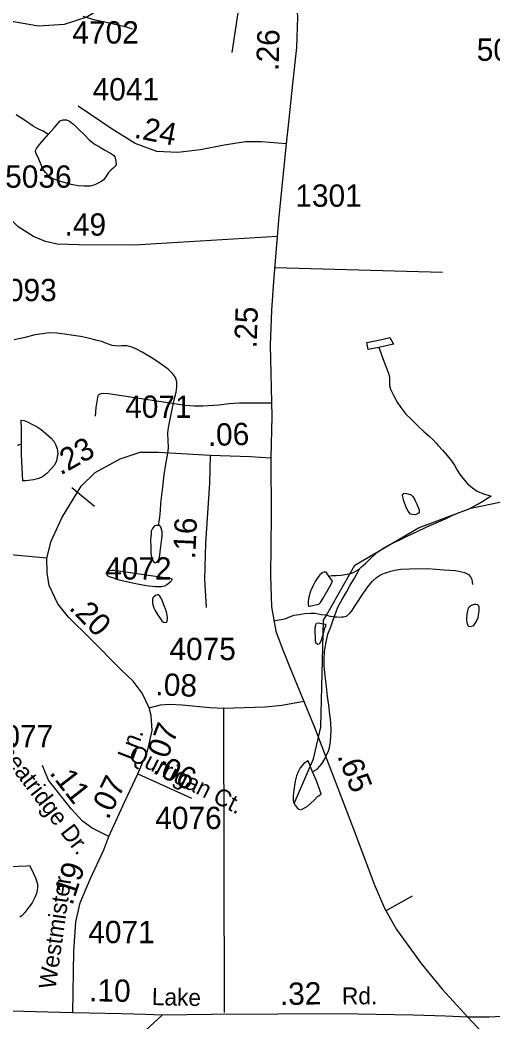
# Model space of a CAD drawing. Extents: x 2001466 to 2224147, y 644118 to 847247.
# Drawn here: x 2062991 to 2065640, y 683500 to 689110 of the extents above; entities that cross this region are included whole.
import ezdxf

# ---------------------------------------------------------------- set-up
doc = ezdxf.new("R2010")
doc.units = 0
for name, color, linetype in [('Exist Hydrographic Misc Water Feature', 7, 'Continuous'), ('Exist Road Non-System Type 51', 7, 'Continuous'), ('Exist Road Secondary Mileage Hundredths English Label', 7, 'Continuous'), ('Exist Road Secondary Type 51 Attributed', 7, 'Continuous'), ('Exist Road Secondary Type 51 Label', 7, 'Continuous'), ('Exist Road Secondary Type 51 Number Label', 7, 'Continuous')]:
    doc.layers.add(name, color=color, linetype=linetype)

msp = doc.modelspace()

# ---------------------------------------------------------------- linework, layer by layer
at = {"layer": 'Exist Hydrographic Misc Water Feature'}
for points in [[(2063621.2, 689058.4), (2063593.1, 689068.3), (2063571, 689074.1), (2063515.2, 689088.2), (2063465, 689097.9), (2063410.8, 689110.1), (2063344.8, 689129.9)], [(2063150.2, 688471.4), (2063140.1, 688475.4), (2063120.1, 688487.4), (2063090.1, 688501.6), (2063063.9, 688515.4), (2063022, 688545.2), (2062970, 688579.1)], [(2063150.2, 688471.4), (2063182, 688507.6), (2063216, 688545.8), (2063231.8, 688551.6), (2063250.3, 688551.6), (2063267.9, 688543.6), (2063292.3, 688525.8), (2063320.4, 688498), (2063350.1, 688470), (2063380.5, 688438.2), (2063412, 688413.9), (2063436.2, 688400.1), (2063466.4, 688382.1), (2063498.2, 688364.4), (2063514.4, 688354.2), (2063522.6, 688344.4), (2063528.3, 688320.4), (2063528.7, 688302.1), (2063524.4, 688292.2), (2063512.7, 688280.2), (2063498.6, 688270.2), (2063486.5, 688256.2), (2063470.7, 688232.3), (2063458.6, 688216.2), (2063448.3, 688208.1), (2063432.8, 688198.3), (2063409, 688188.1), (2063382.9, 688180.2), (2063350.5, 688179.9), (2063316.5, 688181.8), (2063276.5, 688189.9), (2063218.9, 688205.9), (2063174.8, 688221.5), (2063158.6, 688231.7), (2063148.6, 688239.7), (2063132.8, 688257.5), (2063118.6, 688277.5), (2063096.7, 688331.5), (2063080.1, 688367.7), (2063076.6, 688379.6), (2063082.3, 688391.3), (2063102.4, 688415.4), (2063150.2, 688471.4)], [(2063766, 686281.1), (2063768.2, 686291.3), (2063770.1, 686303.2), (2063774.2, 686327.3), (2063778.1, 686363.3), (2063779.9, 686405.1), (2063785.9, 686449.3), (2063791.4, 686495), (2063797.8, 686563.1), (2063807.8, 686623.2), (2063817.4, 686673.2), (2063821.5, 686713.2), (2063820.9, 686761.2), (2063819.3, 686787.4), (2063819.3, 686799.1), (2063823, 686829.4), (2063836.9, 686903.1), (2063849, 686957.2), (2063856.8, 686991.4), (2063864.8, 687027.5), (2063868.7, 687057.3), (2063868.5, 687085.3), (2063860.7, 687109.2), (2063844.3, 687131.2), (2063820.3, 687155.1), (2063776.2, 687186.9), (2063734.2, 687214.8), (2063674.3, 687250.6), (2063640.3, 687268.8), (2063616.5, 687278.5), (2063590.2, 687286.5), (2063560.5, 687286.6), (2063540.6, 687284.7), (2063506.4, 687288.7), (2063470.5, 687300.6), (2063446.3, 687310.3), (2063422.1, 687316.4), (2063402.2, 687322.3), (2063364.1, 687330.1), (2063330.4, 687338), (2063290.2, 687344.1), (2063240.2, 687352.1), (2063196.1, 687358), (2063152.2, 687359.8), (2063116.4, 687353.9), (2063074.1, 687347.7), (2063020.4, 687333.6), (2062958.1, 687319.5)], [(2065000.2, 687277.2), (2064939.9, 687265.2), (2064933.7, 687305.1), (2065018, 687321.1), (2065061.9, 687333.6), (2065081.8, 687295.6), (2065000.2, 687277.2)], [(2065000.2, 687277.2), (2065010.2, 687253.3), (2065018.2, 687229.4), (2065037.9, 687175.3), (2065054.3, 687133.5), (2065060.3, 687109.5), (2065060.5, 687085.5), (2065060.7, 687063.6), (2065066.6, 687043.6), (2065084.5, 687005.6), (2065102.7, 686971.6), (2065122.8, 686941.8), (2065152.5, 686903.6), (2065178.8, 686877.7), (2065220.6, 686835.7), (2065252.8, 686806.1), (2065282.7, 686780.1), (2065305.1, 686760.1), (2065320.7, 686741.9), (2065335, 686725.9), (2065357, 686702.3), (2065380.8, 686674.4), (2065401.5, 686650.1), (2065423.4, 686618.4), (2065439.2, 686590.4), (2065455.6, 686564.5), (2065479.6, 686534.5), (2065497.4, 686514.3), (2065525.7, 686490.5), (2065551.2, 686472.5), (2065587.4, 686458.4), (2065619.4, 686448.8), (2065629.5, 686444.8)], [(2064707, 685778.8), (2064865.9, 686058.3), (2065222.9, 686267.6), (2065514.9, 686376.5), (2065805.8, 686436.2), (2066222.7, 686460.5), (2066438.8, 686518.5), (2066613.7, 686777.4), (2066871.9, 686913.2)], [(2062999.5, 686733.6), (2062999.3, 686819.6), (2062997.4, 686869.4), (2063013.2, 686867.7), (2063033.1, 686861.5), (2063061, 686845.9), (2063087.2, 686831.8), (2063109.6, 686817.9), (2063137.5, 686793.8), (2063165.4, 686770.1), (2063179.7, 686752.1), (2063191.4, 686730), (2063199.6, 686710.1), (2063201.7, 686682.2), (2063199.6, 686662.3), (2063195.5, 686642.2), (2063183.8, 686618), (2063166, 686598), (2063141.6, 686572.1), (2063115.7, 686552.1), (2063095.7, 686543.7), (2063065.9, 686535.7), (2063038, 686531.8), (2063022, 686529.8), (2063005.8, 686529.8), (2062999.5, 686675.5), (2062999.5, 686733.6)], [(2062999.5, 686733.6), (2062993.5, 686733.7), (2062975.5, 686727.5)], [(2064892.1, 686037.4), (2064904.2, 686049.3), (2064928, 686069.7), (2064958.1, 686099.6), (2064994.4, 686133.4), (2065032, 686157.7), (2065066, 686175.7), (2065114, 686197.7), (2065160.1, 686219.9), (2065212.2, 686244), (2065270, 686272.2), (2065333.8, 686300.2), (2065377.9, 686320.3), (2065419.5, 686340.3), (2065465.4, 686358.5), (2065503.6, 686372.6), (2065551.6, 686398.6), (2065583.5, 686416.5), (2065615.3, 686436.8), (2065629.5, 686444.8)], [(2065213.4, 686400), (2065225.7, 686368.1), (2065225.9, 686362), (2065225.9, 686351.8), (2065221.4, 686348.1), (2065215.7, 686344.1), (2065201.7, 686339.7), (2065189.8, 686341.9), (2065177.8, 686343.7), (2065165.7, 686359.8), (2065154, 686381.8), (2065139.6, 686417.6), (2065133.5, 686447.8), (2065133.7, 686453.8), (2065139.8, 686459.8), (2065147.8, 686461.8), (2065163.6, 686457.8), (2065181.9, 686451.8), (2065191.7, 686441.8), (2065199.5, 686428), (2065205.6, 686413.7), (2065213.4, 686400)], [(2063766, 686281.1), (2063752.4, 686281.1), (2063742.4, 686277), (2063731.9, 686263.1), (2063726.2, 686249), (2063724.5, 686231), (2063722.3, 686203), (2063722.5, 686155.1), (2063724.3, 686123.1), (2063726.6, 686102.9), (2063730.5, 686091.4), (2063736.4, 686081.2), (2063740.5, 686075.3), (2063744.4, 686073.1), (2063750.6, 686073.4), (2063756.3, 686075.3), (2063766.6, 686085.2), (2063772.1, 686101.3), (2063776.6, 686133.1), (2063784, 686193.2), (2063786.3, 686221.3), (2063786.3, 686245.2), (2063782.2, 686265.3), (2063778.3, 686275.2), (2063770.3, 686281.3), (2063766, 686281.1)], [(2063660.8, 686009.1), (2063838.8, 685983.3), (2063840.8, 685977.3), (2063836.9, 685969.4), (2063832.4, 685963.2), (2063820.5, 685953.2), (2063812.7, 685947.1), (2063800.8, 685941.2), (2063782.6, 685937.5), (2063748.7, 685937.4), (2063696.9, 685943.2), (2063630.8, 685954.8), (2063570.8, 685968.8), (2063541, 685976.9), (2063510.9, 685986.8), (2063492.6, 685992.8), (2063484.8, 685996.8), (2063478.5, 686002.6), (2063482.8, 686014.6), (2063486.5, 686024.6), (2063492.6, 686028.9), (2063504.5, 686030.8), (2063518.5, 686030.7), (2063542.7, 686027), (2063660.8, 686009.1)], [(2064720.5, 685996.9), (2064706.3, 686018.9), (2064694.4, 686019.1), (2064686.4, 686017.1), (2064670.5, 686004.9), (2064658.8, 685988.8), (2064644.4, 685967), (2064630.3, 685940.8), (2064618.6, 685913), (2064608.5, 685878.8), (2064604.8, 685857), (2064604.8, 685838.8), (2064606.9, 685828.7), (2064610.8, 685829), (2064664.7, 685839), (2064674.6, 685848.9), (2064688.7, 685873.1), (2064732.8, 685951.2), (2064740.4, 685969.1), (2064720.5, 685996.9)], [(2064628.4, 684901.1), (2064654.5, 684915), (2064668.6, 684931.1), (2064680.3, 684945.2), (2064698.1, 684973.3), (2064708.2, 684995.3), (2064716.4, 685013.1), (2064724.2, 685035.4), (2064730.3, 685071.4), (2064734.2, 685133.3), (2064732.2, 685179.4), (2064725.8, 685221.4), (2064719.7, 685273.4), (2064713.5, 685323.4), (2064707.6, 685379.1), (2064699.8, 685439.1), (2064693.4, 685493.2), (2064693.4, 685530.9), (2064695.3, 685573.2), (2064703.1, 685617.1), (2064714.9, 685671.2), (2064730.9, 685713), (2064746.7, 685757.3), (2064760.7, 685797.3), (2064770.5, 685823.4), (2064782.8, 685843), (2064796.6, 685869.4), (2064810.7, 685891.1), (2064821, 685911.1), (2064840.6, 685945.4), (2064864.2, 685985.2), (2064882.3, 686019.4), (2064892.1, 686037.4)], [(2064720.5, 685996.9), (2064738.1, 686001.1), (2064760.7, 686000.9), (2064790.4, 686001.3), (2064822.6, 686007.4), (2064848.6, 686013.2), (2064864.4, 686021.3), (2064880.6, 686029.4), (2064892.1, 686037.4)], [(2063760.8, 685781.4), (2063777.2, 685757.4), (2063785.4, 685747.2), (2063795.1, 685739.3), (2063802.9, 685737.3), (2063811.3, 685739.3), (2063815.4, 685743.5), (2063817, 685763.5), (2063815, 685777.2), (2063811.1, 685797.3), (2063800.8, 685827.2), (2063782.8, 685869.3), (2063773.1, 685885.4), (2063764.7, 685891.1), (2063758.8, 685891.2), (2063749.2, 685889), (2063736.9, 685877.1), (2063733.2, 685867.1), (2063733.2, 685857), (2063733, 685845.2), (2063735, 685835.2), (2063741, 685819.3), (2063748.9, 685801.4), (2063760.8, 685781.4)], [(2065492.7, 685784.5), (2065491.1, 685754.8), (2065492.7, 685734.6), (2065494.8, 685730.7), (2065499.1, 685720.7), (2065502.6, 685716.5), (2065515.1, 685714.6), (2065524.7, 685718.8), (2065532.7, 685720.9), (2065542.5, 685734.8), (2065548.7, 685748.9), (2065556.5, 685764.7), (2065558.7, 685778.5), (2065562.4, 685800.7), (2065562.6, 685822.6), (2065558.9, 685832.5), (2065554.4, 685836.8), (2065546.6, 685838.8), (2065534.7, 685838.6), (2065519, 685832.5), (2065508.7, 685824.7), (2065500.5, 685816.6), (2065496.4, 685802.6), (2065492.7, 685784.5)], [(2064526.7, 684723.4), (2064633.7, 684973.8), (2064675.8, 685150.2), (2064690.8, 685750.2), (2064707, 685778.8)], [(2064677.4, 685638.8), (2064673.1, 685628.9), (2064665.9, 685616.6), (2064659, 685613.2), (2064653.2, 685616.9), (2064648.9, 685619.2), (2064645.4, 685633.1), (2064645.4, 685651), (2064644.8, 685689.1), (2064644.8, 685709), (2064647.1, 685722.9), (2064649.1, 685729.1), (2064651, 685732.8), (2064659, 685734.9), (2064701, 685727.3), (2064701, 685717.1), (2064695.1, 685699), (2064688.9, 685673.1), (2064677.4, 685638.8)], [(2064628.4, 684901.1), (2064604.2, 684963.2), (2064580.2, 684947), (2064560.5, 684923.2), (2064548.4, 684901.1), (2064538.8, 684879), (2064532.5, 684849.1), (2064528.6, 684825), (2064522.6, 684784.9), (2064520.8, 684762.9), (2064521.2, 684745), (2064522.6, 684731), (2064531, 684715.1), (2064542.7, 684699.1), (2064553, 684691.1), (2064561.2, 684689.1), (2064570.6, 684692.8), (2064598.9, 684707.3), (2064638.5, 684743), (2064656.7, 684763.4), (2064664.7, 684767), (2064677, 684777.3), (2064650.6, 684851.1), (2064628.4, 684901.1)], [(2062931.8, 684371.8), (2063029.8, 684374), (2063043.8, 684376.3), (2063054, 684360.2), (2063078, 684308.3), (2063088.1, 684274.3), (2063088.3, 684252.4), (2063086.2, 684238.1), (2063082.1, 684220.5), (2063072.3, 684194.4), (2063058.5, 684168.1), (2063040.5, 684144.1), (2063018.3, 684114.1), (2063000.3, 684094.2), (2062990.5, 684086.4)]]:
    msp.add_lwpolyline(points, dxfattribs=at)
at = {"layer": 'Exist Road Non-System Type 51'}
for p, q in [((2064417.1, 687725), (2065356.9, 687698.5)), ((2063281.1, 686493.2), (2063408.4, 686388.4)), ((2064130.8, 685257.1), (2064133.3, 683552.8))]:
    msp.add_line(p, q, dxfattribs=at)
for points in [[(2063805.6, 689732.4), (2063944.2, 689695.4), (2064044.4, 689640.5), (2064115.5, 689569.3), (2064199.5, 689433.5), (2064222.1, 689346.2), (2064222.1, 689226.5), (2064176.9, 688929)], [(2063414.4, 686892), (2063417.3, 686940), (2063426.5, 686997.8), (2063430.8, 687011.7), (2063445, 687019.4), (2063457, 687021.2), (2063487, 687018.5), (2063915.6, 686953.8), (2063967.6, 686950.7), (2064015.6, 686949.8), (2064105.7, 686955.9), (2064159.8, 686962.8), (2064219.9, 686967.6), (2064399.7, 686967.9)], [(2064707, 685778.8), (2064727.5, 685773.2), (2064755.4, 685768.7), (2064765.4, 685768.5), (2064783.4, 685766.1), (2064793.4, 685767.9), (2064801.5, 685769.7), (2064819.5, 685773.4), (2064837.9, 685789), (2064850.2, 685804.7), (2064862.5, 685822.5), (2064872.9, 685840.3), (2064912.1, 685899.5), (2064938.9, 685936.9), (2064965.5, 685968.4), (2064988, 685989.9), (2065004.2, 685999.6), (2065022.4, 686009.2), (2065032.4, 686013), (2065050.6, 686018.7), (2065060.6, 686022.5), (2065090.8, 686029.8), (2065122.9, 686035.2), (2065173, 686038.2), (2065273, 686040.1), (2065366.8, 686032.2), (2065430.8, 686028.9), (2065480.5, 686017.9), (2065492.4, 686011.7), (2065502.3, 686005.5), (2065514, 685993.2), (2065517.9, 685985.1), (2065521.7, 685977.1), (2065525.1, 685949)], [(2064411, 685745.6), (2064473.2, 685758.4), (2064523.6, 685777.4), (2064553.7, 685782.8), (2064583.8, 685788.2), (2064617.9, 685789.5), (2064643.9, 685788.9), (2064677.7, 685782.3), (2064703.7, 685779.7), (2064707, 685778.8)], [(2064130.8, 685257.1), (2064363.6, 685265.3), (2064457.1, 685274.3), (2064582.5, 685296.8)], [(2065045.5, 684126.3), (2065188.6, 684205.9)]]:
    msp.add_lwpolyline(points, dxfattribs=at)
at = {"layer": 'Exist Road Secondary Type 51 Attributed'}
for points in [[(2064306.6, 689747.5), (2064354, 689676), (2064445.1, 689537.9), (2064498, 689407.6), (2064535.1, 689250.5), (2064544.5, 689128.9), (2064539.8, 688956.7), (2064517.3, 688753.8), (2064495.6, 688554.9), (2064480.6, 688417.5)], [(2063642.3, 689406), (2063574.9, 689293.1), (2063478.6, 689198.3), (2063365, 689127.3), (2063237.2, 689086.2), (2063095.1, 689076.8), (2062954.7, 689100.4), (2062794.1, 689151), (2062684.5, 689164.4), (2062584.3, 689154.1), (2062486.8, 689132)], [(2064480.6, 688417.5), (2064341.8, 688427.7), (2064253.4, 688429.3), (2064133.5, 688410.4), (2064002.5, 688383.5), (2063874.7, 688369.3), (2063756.3, 688374.1), (2063636, 688419.1), (2063506.6, 688499.6), (2063316.1, 688628.3)], [(2064431.7, 687898.2), (2063630.2, 687849.6), (2063319.5, 687851.2), (2063198.8, 687855), (2063132.6, 687870.6), (2063066.4, 687897.9), (2062980.8, 687952.4), (2062922.4, 688010.9), (2062864, 688096.6), (2062801.7, 688221.2), (2062743.3, 688330.3), (2062700.5, 688396.5), (2062657.7, 688437.8), (2062599.7, 688480.5), (2062505.8, 688514.6), (2062145.7, 688598.9)], [(2064480.6, 688417.5), (2064441.2, 688010.9), (2064431.7, 687898.2)], [(2064431.7, 687898.2), (2064410.4, 687646.1), (2064399.4, 687485), (2064391.5, 687290.8), (2064401.7, 686889.7), (2064395.4, 686659.2)], [(2063141.7, 686097), (2063165.8, 686191.8), (2063225.7, 686322.8), (2063333, 686499.7), (2063412.3, 686576.3), (2063551.2, 686654.4), (2063663.2, 686690), (2063765.8, 686690), (2064056.2, 686674.2)], [(2064056.2, 686674.2), (2064051.8, 686517.1), (2064028.9, 686180.7), (2064024.6, 685979.4), (2064032.9, 685821.5)], [(2064056.2, 686674.2), (2064279.8, 686666.3), (2064395.4, 686659.2)], [(2064395.4, 686659.2), (2064397, 686333.9), (2064394.6, 685997.5), (2064399.4, 685825.4), (2064423.3, 685689.1), (2064458.3, 685594.1), (2064500.7, 685490.3), (2064638.4, 685154.3), (2064866.5, 684560.5), (2064974.7, 684271.4), (2065031.7, 684136.9), (2065098.9, 684018.5), (2065237.7, 683827.1), (2065354.7, 683683.4), (2065499, 683527.8)], [(2063141.7, 686097), (2062958.6, 686114.4), (2062753.5, 686138.1), (2062621, 686161.8)], [(2063713.9, 685259.6), (2063674.3, 685342.2), (2063624.6, 685407.7), (2063559.9, 685469.3), (2063383.5, 685647.8), (2063262.8, 685767.8), (2063202.8, 685841.2), (2063154.3, 685943.8), (2063142.5, 686015.7), (2063141.7, 686097)], [(2063713.9, 685259.6), (2063778.3, 685275.5), (2063826.2, 685280.7), (2063898.1, 685275.5), (2064053, 685260.8), (2064130.8, 685257.1)], [(2063651.2, 684888.9), (2063705, 685016.9), (2063731.5, 685133), (2063726, 685215.9), (2063713.9, 685259.6)], [(2063488.7, 684539.7), (2063395.6, 684585.5), (2063340.4, 684625), (2063277.2, 684694.5), (2063150.6, 684854), (2063117.5, 684936.9)], [(2063488.7, 684539.7), (2063575.3, 684731.9), (2063651.2, 684888.9)], [(2063651.2, 684888.9), (2063951.8, 684753.3)], [(2063286, 683551.6), (2063291.6, 683895.7), (2063302.7, 684061.6), (2063327.4, 684168.1), (2063383.5, 684300.8), (2063459.3, 684464.2), (2063488.7, 684539.7)], [(2067078.2, 684058), (2066921.2, 684007.6), (2066719.6, 683929.4), (2066353.7, 683777.4), (2066101, 683672.1), (2065928.6, 683602), (2065775.1, 683547.8), (2065689.8, 683530.3), (2065618.2, 683526.5), (2065499, 683527.8)], [(2063286, 683551.6), (2063077.7, 683557.9), (2062681.2, 683567.9), (2062329.2, 683574.2)], [(2062552.8, 681509.3), (2062603.2, 681588.2), (2062728.7, 681777.3), (2062829.7, 681925.7), (2062903.8, 682052), (2062974.8, 682205.2), (2063019, 682313), (2063075, 682472.4), (2063127.1, 682698.2), (2063169.7, 682896.8), (2063208.4, 682980.5), (2063244.6, 683045.2), (2063312.5, 683113.1), (2063440.3, 683234.7), (2063629.7, 683395.4), (2063787.4, 683539.1)], [(2063787.4, 683539.1), (2063693.2, 683542.8), (2063559, 683545.3), (2063286, 683551.6)], [(2065499, 683527.8), (2065374.8, 683532.8), (2065192.8, 683539.1), (2064778.1, 683546.6), (2064434.9, 683544.1), (2064063.4, 683541.6), (2063787.4, 683539.1)], [(2065499, 683527.8), (2065653.4, 683360.8), (2065812, 683171.5)]]:
    msp.add_lwpolyline(points, dxfattribs=at)

# ---------------------------------------------------------------- texts
at = {"layer": 'Exist Road Secondary Mileage Hundredths English Label'}
for s, rotation, p in [('.26', 88.4245, (2064438.7, 688824.8)), ('.24', 348.526, (2063625.6, 688452.7)), ('.49', 359.7135, (2063240.1, 687903.8)), ('.25', 87.9498, (2064315.1, 687271.2)), ('.06', 1.5915, (2064044, 686725.1)), ('.23', 29.3633, (2063217.4, 686559.5)), ('.16', 87.3499, (2063971.8, 686090.1)), ('.20', 314.5975, (2063260.1, 685815)), ('.08', 357.5534, (2063747.4, 685330.4)), ('.07', 69.154, (2063800, 684926)), ('.65', 291.6621, (2064766.3, 684989.8)), ('.06', 333.2026, (2063728.4, 684898.1)), ('.11', 307.8627, (2063152, 684894.3)), ('.07', 64.0208, (2063484.8, 684628.9)), ('.19', 71.5725, (2063283.1, 684148.6)), ('.10', 359.0039, (2063377.3, 683616.4)), ('.32', 1.1167, (2064447.4, 683594.5))]:
    msp.add_text(s, height=125, rotation=rotation, dxfattribs=at).set_placement(p)
at = {"layer": 'Exist Road Secondary Type 51 Label'}
for s, rotation, p in [('Wheatridge Dr.', 307.3933, (2062796.7, 685106.3)), ('Ln.', 69.154, (2063621.9, 684959.6)), ('Qurrigan Ct.', 333.2026, (2063592, 684973.1)), ('Westmister', 81.8736, (2063189.3, 683680.4)), ('Lake', 358.7678, (2063728.2, 683595.2)), ('Rd.', 0.3436, (2064794.1, 683598.5))]:
    msp.add_text(s, height=95, rotation=rotation, dxfattribs=at).set_placement(p)
at = {"layer": 'Exist Road Secondary Type 51 Number Label'}
for s, p in [('4702', (2063284, 688978.7)), ('5015', (2065548.9, 688882.1)), ('4041', (2063397.4, 688660.4)), ('5036', (2062907.8, 688171.5)), ('1301', (2064532.8, 688064.9)), ('5093', (2062824.5, 687536.1)), ('4071', (2063579.8, 686882.9)), ('4072', (2063467.4, 685977.6)), ('4075', (2063827.7, 685526.4)), ('4077', (2062804.7, 685037.8)), ('4076', (2063748.2, 684580.4)), ('4071', (2063372.9, 683941.6))]:
    msp.add_text(s, height=125, dxfattribs=at).set_placement(p)

doc.saveas('drawing.dxf')
